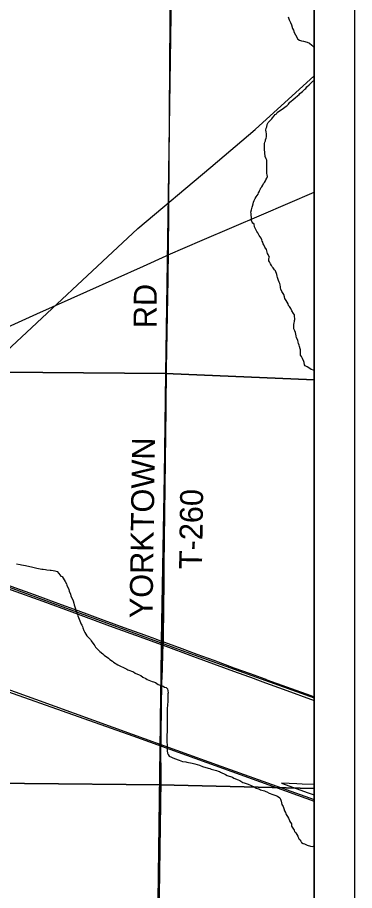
# Model space of a CAD drawing. Extents: x 0 to 34, y 0 to 22.
# Drawn here: x 8.166 to 9, y 17.171 to 19.332 of the extents above; entities that cross this region are included whole.
import ezdxf

# ---------------------------------------------------------------- set-up
doc = ezdxf.new("R2010")
doc.units = 0
for name, color, linetype in [('Default', 7, 'Continuous'), ('GM_X_Minor_River', 7, 'Continuous'), ('GM_X_Rail_Line', 7, 'Continuous'), ('GM_X_Section', 7, 'Continuous'), ('GM_X_State_Route', 7, 'Continuous'), ('GM_X_Township', 7, 'Continuous'), ('GM_X_Township_Road', 7, 'Continuous'), ('GM_X_Township_Road_Text', 7, 'Continuous'), ('GM_X_US_Route', 7, 'Continuous'), ('SH_Cut_Line', 7, 'Continuous'), ('SH_Data', 7, 'Continuous')]:
    doc.layers.add(name, color=color, linetype=linetype)

msp = doc.modelspace()

# ---------------------------------------------------------------- linework, layer by layer
at = {"layer": 'Default'}
for points in [[(8.9, 18.4355), (8.9, 19.4359), (8.547, 19.4493), (8.532, 18.4506)], [(8.9, 17.4232), (8.9, 18.4355), (8.532, 18.4506), (8.5188, 17.4323)], [(8.9, 16.4273), (8.9, 17.4232), (8.5188, 17.4323), (8.5041, 16.4364)], [(8.9, 17.4075), (8.9, 17.4333), (8.8706, 17.4345), (8.8574, 17.435), (8.8191, 17.4367), (8.8851, 17.4129)]]:
    msp.add_lwpolyline(points, close=True, dxfattribs=at)
at = {"layer": 'GM_X_Minor_River'}
for points in [[(8.8357, 19.3338), (8.8384, 19.3266), (8.8418, 19.3197), (8.8437, 19.3144), (8.8464, 19.3053), (8.8487, 19.3012), (8.8507, 19.2955), (8.8537, 19.2894), (8.8599, 19.2788), (8.864, 19.2765), (8.869, 19.2743), (8.8735, 19.2739), (8.8827, 19.2709), (8.8887, 19.2691), (8.8941, 19.2638), (8.8983, 19.26), (8.9, 19.2575)], [(8.782, 18.758), (8.7783, 18.7637), (8.7753, 18.7691), (8.7742, 18.7717), (8.7734, 18.7759), (8.7712, 18.7786), (8.7708, 18.7816), (8.769, 18.7862), (8.7637, 18.7927), (8.7607, 18.7988), (8.7585, 18.8022), (8.7525, 18.8144), (8.7514, 18.8205), (8.7481, 18.8232), (8.7466, 18.8259), (8.7447, 18.8297), (8.7451, 18.8324), (8.7448, 18.8365), (8.7444, 18.8437), (8.7441, 18.8468), (8.7437, 18.8502), (8.7449, 18.8563), (8.7469, 18.8627), (8.7476, 18.8654), (8.7492, 18.871), (8.7496, 18.8748), (8.7519, 18.879), (8.7543, 18.8843), (8.7569, 18.8884), (8.7616, 18.8952), (8.7627, 18.8979), (8.7643, 18.9009), (8.765, 18.9035), (8.767, 18.9077), (8.7681, 18.9104), (8.7708, 18.9134), (8.7727, 18.9168), (8.775, 18.9209), (8.777, 18.9236), (8.7793, 18.9277), (8.7808, 18.9304), (8.7827, 18.9349), (8.7843, 18.9387), (8.7839, 18.9425), (8.7832, 18.9463), (8.7832, 18.9493), (8.7829, 18.9531), (8.7826, 18.9619), (8.7826, 18.9653), (8.7834, 18.9717), (8.7827, 18.9789), (8.7812, 18.9824), (8.7786, 18.9885), (8.778, 18.9972), (8.7769, 19.0063), (8.777, 19.0204), (8.7778, 19.0238), (8.7793, 19.0272), (8.7801, 19.0298), (8.7813, 19.0332), (8.7821, 19.0367), (8.7825, 19.0393), (8.7822, 19.0446), (8.7814, 19.0496), (8.7807, 19.0534), (8.7815, 19.0579), (8.7827, 19.0617), (8.7839, 19.0674), (8.7866, 19.0723), (8.7923, 19.0783), (8.795, 19.081), (8.7973, 19.084), (8.8015, 19.0885), (8.8034, 19.0923), (8.8068, 19.0938), (8.8084, 19.0972), (8.8122, 19.0998), (8.8213, 19.1054), (8.8309, 19.1125), (8.8336, 19.1148), (8.8366, 19.1178), (8.8401, 19.1223), (8.8427, 19.1242), (8.8485, 19.1291), (8.8531, 19.1336), (8.8592, 19.1385), (8.8626, 19.1419), (8.8645, 19.1445), (8.871, 19.149), (8.8737, 19.1513), (8.8767, 19.155), (8.8798, 19.1565), (8.8821, 19.1603), (8.8878, 19.1652), (8.8924, 19.1704), (8.8966, 19.1746), (8.9, 19.1767)], [(8.9, 18.458), (8.8982, 18.4593), (8.8929, 18.4609), (8.8895, 18.4636), (8.8827, 18.4674), (8.8778, 18.4701), (8.8759, 18.4728), (8.8756, 18.4781), (8.8745, 18.4808), (8.8715, 18.488), (8.8689, 18.493), (8.8666, 18.4961), (8.8667, 18.5006), (8.8663, 18.5056), (8.866, 18.5097), (8.8653, 18.5124), (8.8642, 18.5177), (8.8634, 18.5208), (8.8612, 18.525), (8.8609, 18.5288), (8.8598, 18.5333), (8.8568, 18.539), (8.8557, 18.5444), (8.8549, 18.5482), (8.8538, 18.5524), (8.852, 18.5566), (8.8501, 18.5615), (8.8494, 18.5653), (8.8498, 18.5687), (8.8502, 18.5725), (8.8506, 18.5767), (8.8514, 18.5793), (8.8518, 18.582), (8.8526, 18.585), (8.8522, 18.5877), (8.8515, 18.5911), (8.8512, 18.596), (8.8493, 18.5995), (8.8452, 18.606), (8.8422, 18.6121), (8.8392, 18.6166), (8.8366, 18.6193), (8.8355, 18.6231), (8.8332, 18.6273), (8.8306, 18.6315), (8.8276, 18.6365), (8.8269, 18.6411), (8.8251, 18.6468), (8.8202, 18.654), (8.8176, 18.6597), (8.8169, 18.6628), (8.8169, 18.6654), (8.8158, 18.6704), (8.8154, 18.6734), (8.8139, 18.6769), (8.8117, 18.6814), (8.8095, 18.6887), (8.8088, 18.6921), (8.8077, 18.6963), (8.8043, 18.705), (8.8021, 18.7077), (8.7983, 18.7123), (8.7961, 18.7154), (8.7942, 18.7184), (8.792, 18.7226), (8.7897, 18.7272), (8.7878, 18.7299), (8.7879, 18.7329), (8.7883, 18.7355), (8.7894, 18.7386), (8.7883, 18.7412), (8.7865, 18.7454), (8.785, 18.7481), (8.7827, 18.7542), (8.782, 18.758)], [(8.1637, 17.9795), (8.1724, 17.978), (8.1762, 17.9773), (8.1861, 17.9758), (8.1887, 17.9751), (8.2009, 17.9721), (8.2104, 17.9699), (8.2138, 17.9687), (8.2264, 17.9669), (8.2298, 17.9662), (8.2355, 17.9654), (8.2389, 17.9651), (8.2465, 17.9643), (8.2492, 17.964), (8.2541, 17.9632), (8.2583, 17.9625), (8.264, 17.961), (8.2686, 17.9561), (8.2735, 17.9493), (8.2762, 17.9481), (8.2819, 17.9398), (8.2838, 17.936), (8.2873, 17.93), (8.2881, 17.9273), (8.2927, 17.9159), (8.2942, 17.9118), (8.2973, 17.9046), (8.2984, 17.9008), (8.2992, 17.8977), (8.3023, 17.8921), (8.3034, 17.8879), (8.3054, 17.8822), (8.3061, 17.8784), (8.3096, 17.8682), (8.3104, 17.8647), (8.3142, 17.8545), (8.3154, 17.8507), (8.3185, 17.8424), (8.32, 17.8386), (8.3238, 17.8306), (8.325, 17.828), (8.3265, 17.8246), (8.3277, 17.8215), (8.3304, 17.8151), (8.3327, 17.8094), (8.3354, 17.806), (8.3377, 17.8011), (8.3407, 17.7984), (8.3464, 17.7924), (8.348, 17.7893), (8.3552, 17.7803), (8.3575, 17.7765), (8.359, 17.7738), (8.3663, 17.7663), (8.3697, 17.7625), (8.3774, 17.7568), (8.3808, 17.7534), (8.3911, 17.7462), (8.3945, 17.7425), (8.401, 17.7387), (8.4036, 17.7364), (8.4143, 17.7296), (8.4174, 17.7278), (8.4314, 17.7214), (8.4364, 17.7187), (8.4394, 17.7172), (8.4527, 17.712), (8.4573, 17.7093), (8.4672, 17.7048), (8.471, 17.7029), (8.476, 17.6988), (8.4839, 17.6962), (8.487, 17.6935), (8.4995, 17.6886)], [(8.4995, 17.6886), (8.5026, 17.6879), (8.5075, 17.6856), (8.514, 17.6811), (8.5193, 17.6796), (8.5266, 17.6766), (8.53, 17.6744), (8.5342, 17.6732), (8.5368, 17.6702), (8.5388, 17.6607), (8.5384, 17.6577), (8.5377, 17.6493), (8.5381, 17.6467), (8.5378, 17.6375), (8.537, 17.6322), (8.537, 17.6284), (8.5367, 17.6231), (8.5364, 17.6121), (8.5364, 17.6094), (8.5365, 17.5798), (8.5362, 17.5756), (8.5362, 17.5638), (8.5355, 17.5566), (8.5356, 17.538), (8.536, 17.5316), (8.5361, 17.5194), (8.5365, 17.5167), (8.5376, 17.5107), (8.5392, 17.5073), (8.5411, 17.5039), (8.5548, 17.4975), (8.5658, 17.4937), (8.5742, 17.4907), (8.5825, 17.4892), (8.5852, 17.4885), (8.5985, 17.4863), (8.6049, 17.4844), (8.616, 17.481), (8.624, 17.4777), (8.6376, 17.4739), (8.6422, 17.4728), (8.6449, 17.4717), (8.6582, 17.4679), (8.6624, 17.4668), (8.6658, 17.4657), (8.6684, 17.4642), (8.681, 17.4582), (8.6852, 17.4559), (8.6981, 17.4514), (8.7012, 17.4495), (8.7122, 17.4454), (8.716, 17.4432), (8.724, 17.4386), (8.7266, 17.4379), (8.732, 17.436), (8.7369, 17.4341), (8.7518, 17.4274), (8.7544, 17.4255), (8.7647, 17.4217), (8.7677, 17.4206), (8.7772, 17.4176), (8.7803, 17.4165), (8.7833, 17.415), (8.7887, 17.412), (8.7913, 17.4112), (8.7951, 17.4097), (8.8001, 17.4079), (8.8027, 17.4067), (8.8096, 17.4045), (8.8153, 17.4003), (8.8168, 17.3973), (8.8187, 17.392), (8.8203, 17.3836), (8.823, 17.3791), (8.8249, 17.3742), (8.8268, 17.3681), (8.8295, 17.3639), (8.8303, 17.3605), (8.8364, 17.3503), (8.8391, 17.3446), (8.8399, 17.3416), (8.8437, 17.3359), (8.8441, 17.3306), (8.8506, 17.3207), (8.8514, 17.3173), (8.8544, 17.3135), (8.8571, 17.3097), (8.8598, 17.3052), (8.8621, 17.2991), (8.8648, 17.2965), (8.8671, 17.2931), (8.8686, 17.29), (8.8728, 17.287), (8.8758, 17.2863), (8.8827, 17.2829), (8.8914, 17.281), (8.8964, 17.2803), (8.9, 17.2814)]]:
    msp.add_lwpolyline(points, dxfattribs=at)
at = {"layer": 'GM_X_Rail_Line'}
for points in [[(7.6757, 18.0934), (7.7402, 18.1481), (7.8743, 18.2711), (8.1262, 18.4945), (8.4641, 18.8097), (8.6445, 18.9615), (8.7545, 19.0553), (8.9, 19.1876)], [(7.6757, 18.0934), (8.5713, 17.7661), (8.9, 17.6476)], [(7.4524, 17.8921), (7.9795, 17.7204), (8.4514, 17.5539), (8.9, 17.3924)], [(7.988, 17.7248), (8.2105, 17.6444), (8.4499, 17.5581), (8.669, 17.4791), (8.9, 17.396)]]:
    msp.add_lwpolyline(points, dxfattribs=at)
at = {"layer": 'GM_X_Section'}
for points in [[(7.5241, 19.4466), (8.547, 19.4493), (8.532, 18.4506), (7.5189, 18.4589)], [(8.532, 18.4506), (8.5188, 17.4323), (7.5107, 17.4428), (7.5189, 18.4589)], [(8.5188, 17.4323), (8.5041, 16.4364), (7.4967, 16.4401), (7.5107, 17.4428)]]:
    msp.add_lwpolyline(points, close=True, dxfattribs=at)
at = {"layer": 'GM_X_State_Route'}
for points in [[(8.539, 18.7445), (8.6231, 18.7808), (8.77, 18.8438), (8.9, 18.8995)], [(8.1322, 18.5619), (8.2135, 18.5984), (8.3377, 18.6539), (8.4774, 18.7168), (8.5339, 18.7422), (8.539, 18.7445)]]:
    msp.add_lwpolyline(points, dxfattribs=at)
at = {"layer": 'GM_X_Township'}
msp.add_lwpolyline([(4.5784, 20.3968), (5.284, 20.4086), (5.325, 20.4092), (6.5316, 20.4254), (6.5575, 20.4259), (7.5409, 20.4415), (8.556, 20.4544), (8.5437, 19.4556), (8.5436, 19.4447), (8.5388, 18.7451), (8.5216, 17.7888), (8.5215, 17.7806), (8.5214, 17.7731), (8.5094, 16.832), (8.5093, 16.83), (8.4947, 15.4259), (8.4895, 15.0042)], dxfattribs=at)
at = {"layer": 'GM_X_Township_Road'}
for p, q in [((8.539, 18.7445), (8.5466, 19.4551)), ((8.5262, 17.7785), (8.5272, 17.7863))]:
    msp.add_line(p, q, dxfattribs=at)
msp.add_lwpolyline([(8.9, 14.4215), (8.9, 20.4518), (8.556, 20.4544), (8.5437, 19.4556), (8.5436, 19.4447), (8.5388, 18.7451), (8.5216, 17.7888), (8.5215, 17.7806), (8.5214, 17.7731), (8.5094, 16.832), (8.5093, 16.83), (8.4947, 15.4259), (8.4895, 15.0042), (8.4811, 14.4273), (8.4833, 14.4273), (8.6169, 14.4256), (8.6362, 14.4253), (8.7095, 14.4242), (8.7648, 14.4233), (8.8009, 14.4228), (8.8456, 14.4221)], close=True, dxfattribs=at)
for points in [[(8.5287, 17.9373), (8.5292, 17.9757), (8.5337, 18.3639), (8.5346, 18.4636), (8.5385, 18.6842), (8.539, 18.7445)], [(8.5272, 17.7863), (8.5272, 17.7979), (8.5287, 17.9373)], [(8.5144, 16.9349), (8.5176, 17.1591), (8.5215, 17.4432), (8.5206, 17.5327), (8.52, 17.613), (8.5214, 17.6486), (8.5247, 17.7191), (8.5255, 17.759), (8.5262, 17.7785)]]:
    msp.add_lwpolyline(points, dxfattribs=at)
at = {"layer": 'GM_X_US_Route'}
for points in [[(7.8157, 18.0397), (7.8226, 18.0358), (7.8787, 18.0145), (7.929, 17.9962), (7.9793, 17.978), (8.0286, 17.96), (8.0785, 17.9419), (8.1145, 17.9288), (8.1503, 17.9157), (8.2291, 17.8869), (8.3004, 17.8606), (8.3938, 17.8264), (8.4789, 17.7954), (8.5217, 17.7801), (8.5262, 17.7785), (8.6013, 17.7506), (8.7009, 17.7143), (8.7516, 17.6958)], [(8.1172, 17.9364), (8.1499, 17.9246), (8.2076, 17.9035), (8.2651, 17.8825), (8.3153, 17.864), (8.3797, 17.8405), (8.4295, 17.8221), (8.4801, 17.8037), (8.5074, 17.7937), (8.5218, 17.7883), (8.5272, 17.7863)], [(8.5272, 17.7863), (8.5661, 17.7723), (8.6098, 17.7563), (8.6516, 17.741), (8.7017, 17.7226), (8.7421, 17.7079), (8.7777, 17.695)], [(8.7516, 17.6958), (8.7535, 17.6951), (8.7799, 17.6854)], [(8.7777, 17.695), (8.7805, 17.694), (8.7834, 17.6929)], [(8.7799, 17.6854), (8.8233, 17.6694), (8.9, 17.6415)], [(8.7834, 17.6929), (8.8317, 17.6754), (8.8918, 17.6534), (8.9, 17.6504)]]:
    msp.add_lwpolyline(points, dxfattribs=at)
at = {"layer": 'SH_Cut_Line'}
msp.add_lwpolyline([(8.9, 14.4215), (8.9, 20.9), (2.1, 20.9)], dxfattribs=at)
at = {"layer": 'SH_Data'}
for p, q in [((9, 21), (9, 14)), ((8.9, 20.9), (8.9, 14.1))]:
    msp.add_line(p, q, dxfattribs=at)

# ---------------------------------------------------------------- texts
at = {"layer": 'GM_X_Township_Road_Text'}
for s, rotation, p in [('RD', 89.5063, (8.51, 18.5628)), ('YORKTOWN', 89.1748, (8.5, 17.8446)), ('T-260', 89.1569, (8.6226, 17.9661))]:
    msp.add_text(s, height=0.05682, rotation=rotation, dxfattribs=at).set_placement(p)

doc.saveas('drawing.dxf')
